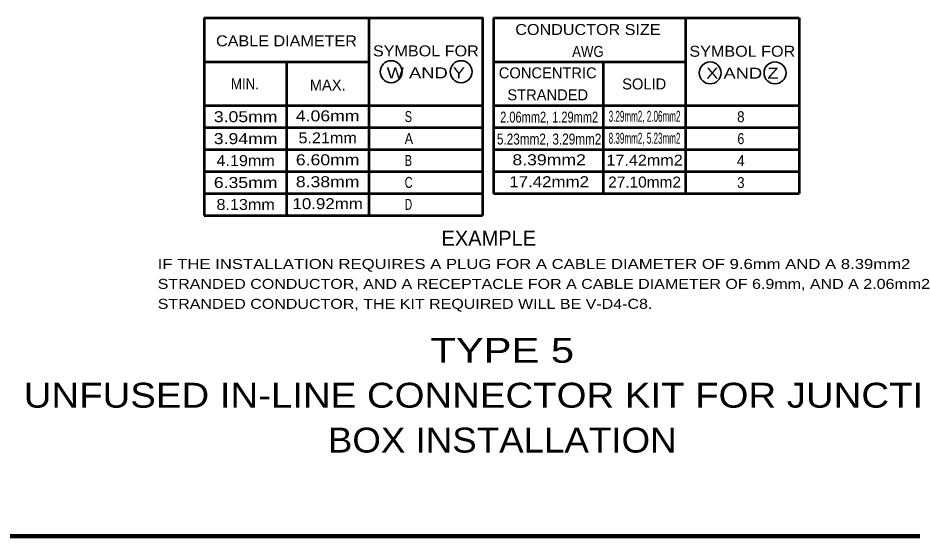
# Model space of a CAD drawing. Extents: x -32 to 824, y -6 to 538.
# Drawn here: x 298.3 to 513.4, y 5.6 to 130.3 of the extents above; entities that cross this region are included whole.
import ezdxf
from ezdxf.enums import TextEntityAlignment as Align

# ---------------------------------------------------------------- set-up
doc = ezdxf.new("R2010")
doc.units = 0
doc.header["$LTSCALE"] = 1.1
doc.layers.add('1', color=7, linetype='Continuous', lineweight=53)

msp = doc.modelspace()

# ---------------------------------------------------------------- linework, layer by layer
at = {"layer": '1'}
for p, q in [((343.129, 130.342), (343.129, 82.822)), ((382.729, 130.342), (382.729, 82.822)), ((412.709, 130.342), (412.709, 88.102)), ((458.909, 130.342), (458.909, 88.102)), ((486.248, 130.342), (486.248, 88.102)), ((343.129, 119.782), (382.729, 119.782)), ((362.929, 119.782), (362.929, 82.822)), ((412.709, 119.782), (458.909, 119.782)), ((439.109, 119.782), (439.109, 88.102)), ((343.129, 109.222), (410.069, 109.222)), ((412.709, 109.222), (486.248, 109.222)), ((343.129, 103.942), (410.069, 103.942)), ((412.709, 103.942), (486.248, 103.942)), ((343.129, 98.662), (410.069, 98.662)), ((412.709, 98.662), (486.248, 98.662)), ((343.129, 93.382), (410.069, 93.382)), ((412.709, 93.382), (486.248, 93.382)), ((343.129, 88.102), (410.069, 88.102)), ((412.709, 88.102), (486.248, 88.102)), ((343.129, 82.822), (410.069, 82.822))]:
    msp.add_line(p, q, dxfattribs=at)
at = {"layer": '1', "lineweight": 158}
msp.add_line((817.398, 5.644), (25.798, 5.644), dxfattribs=at)
at = {"layer": '1'}
for points in [[(343.129, 130.342), (410.069, 130.342), (410.069, 82.822)], [(412.709, 130.342), (458.909, 130.342), (486.248, 130.342)]]:
    msp.add_lwpolyline(points, dxfattribs=at)
at = {"layer": '1', "lineweight": 35}
for centre in [(388.083, 117.381), (404.922, 117.381), (464.825, 117.104), (480.421, 117.104)]:
    msp.add_circle(centre, 2.64, dxfattribs=at)

# ---------------------------------------------------------------- texts
at = {"layer": '1'}
for s, height, width, p in [('CONDUCTOR SIZE', 2.64, 1.1, (435.422, 126.222)), ('SYMBOL FOR', 2.64, 1.1, (396.439, 121.079)), ('AWG', 2.64, 0.9, (435.422, 120.942)), ('SYMBOL FOR', 2.64, 1.1, (472.549, 120.992)), ('W AND Y', 2.64, 1.25, (396.439, 115.799)), ('X AND Z', 2.64, 1.25, (472.549, 115.712)), ('3.05mm', 2.64, 1.2, (353.096, 105.245)), ('4.06mm', 2.64, 1.2, (372.822, 105.44)), ('2.06mm2, 1.29mm2', 2.64, 0.75, (426.089, 105.145)), ('3.29mm2, 2.06mm2', 2.64, 0.55, (449.038, 105.34)), ('8', 2.64, 0.9, (472.194, 105.235)), ('3.94mm', 2.64, 1.2, (353.096, 99.965)), ('5.21mm', 2.64, 1.1, (372.822, 100.16)), ('5.23mm2, 3.29mm2', 2.64, 0.8, (426.089, 99.865)), ('8.39mm2, 5.23mm2', 2.64, 0.55, (449.038, 100.06)), ('6', 2.64, 0.85, (472.194, 99.955)), ('4.19mm', 2.64, 1.1, (353.096, 94.685)), ('6.60mm', 2.64, 1.2, (372.822, 94.88)), ('8.39mm2', 2.64, 1.2, (426.089, 94.888)), ('17.42mm2', 2.64, 1.1, (449.038, 94.791)), ('4', 2.64, 0.95, (472.194, 94.675)), ('6.35mm', 2.64, 1.2, (353.096, 89.405)), ('8.38mm', 2.64, 1.2, (372.822, 89.6)), ('17.42mm2', 2.64, 1.15, (426.089, 89.608)), ('27.10mm2', 2.64, 1.05, (449.038, 89.511)), ('3', 2.64, 0.9, (472.194, 89.395)), ('8.13mm', 2.64, 1.1, (353.096, 84.125)), ('10.92mm', 2.64, 1.15, (372.822, 84.32)), ('TYPE 5', 6, 1.25, (414.807, 47.348)), ('UNFUSED IN-LINE CONNECTOR KIT FOR JUNCTION', 6, 1.15, (414.807, 36.548)), ('BOX INSTALLATION', 6, 1.1, (414.807, 25.748))]:
    msp.add_text(s, height=height, dxfattribs=dict(at, width=width)).set_placement(p, align=Align.CENTER)
for s, height, width, p in [('CABLE DIAMETER', 2.64, 1.1, (345.977, 123.494)), ('MIN.', 2.64, 0.9, (349.567, 113.152)), ('S', 2.64, 0.75, (391.349, 105.27)), ('A', 2.64, 0.85, (391.349, 99.99)), ('B', 2.64, 0.75, (391.349, 94.71)), ('C', 2.64, 0.75, (391.349, 89.43)), ('D', 2.64, 0.7, (391.349, 84.15)), ('IF THE INSTALLATION REQUIRES A PLUG FOR A CABLE DIAMETER OF 9.6mm AND A 8.39mm2', 2.4, 1.25, (331.951, 69.931)), ('STRANDED CONDUCTOR, AND A RECEPTACLE FOR A CABLE DIAMETER OF 6.9mm, AND A 2.06mm2', 2.4, 1.2, (331.951, 65.131)), ('STRANDED CONDUCTOR, THE KIT REQUIRED WILL BE V-D4-C8.', 2.4, 1.2, (331.951, 60.331))]:
    msp.add_text(s, height=height, dxfattribs=dict(at, width=width)).set_placement(p)
for s, p in [('CONCENTRIC', (425.749, 115.789)), ('STRANDED', (425.749, 110.509))]:
    msp.add_text(s, height=2.64, dxfattribs=at).set_placement(p, align=Align.CENTER)
for s, height, p in [('MAX.', 2.64, (368.519, 112.865)), ('SOLID', 2.64, (443.654, 113.123)), ('EXAMPLE', 3.6, (400.204, 75.536))]:
    msp.add_text(s, height=height, dxfattribs=at).set_placement(p)

doc.saveas('drawing.dxf')
